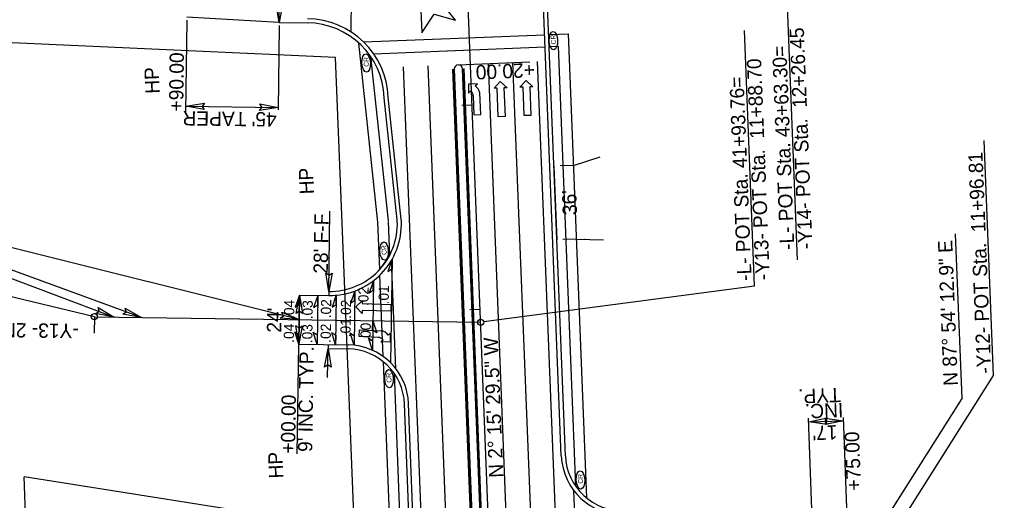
# Model space of a CAD drawing. Extents: x 1627861 to 1629601, y 761281 to 766239.
# Drawn here: x 1628159.8 to 1628635.6, y 764580 to 764815.3 of the extents above; entities that cross this region are included whole.
import ezdxf

# ---------------------------------------------------------------- set-up
doc = ezdxf.new("R2010")
doc.units = 0
for name, color, linetype in [('Cogo Default Point CELL', 7, 'Continuous'), ('Exist Other Culture Sign Leader', 7, 'Continuous'), ('Exist Property Tie Line Text', 7, 'Continuous'), ('Exist Right of Way Line Leader', 7, 'Continuous'), ('Exist Right of Way Monument Leader', 7, 'Continuous'), ('Exist Right of Way Monument Text', 7, 'Continuous'), ('Exist Utilities Gas Meter CELL', 7, 'Continuous'), ('Exist Utilities Gas Meter Cogo Elevation', 7, 'Continuous'), ('Exist Utilities Gas Meter Cogo Number', 7, 'Continuous'), ('Exist Utilities Gas UG Line', 7, 'Continuous'), ('Exist Utilities Other Unknown UG SUE Text', 7, 'Continuous'), ('Exist Utilities Power UG Cable SUE LOS B Cogo Elevation', 7, 'Continuous'), ('Exist Utilities Power UG Cable SUE LOS B Cogo Point CELL', 7, 'Continuous'), ('Exist Utilities Telephone UG Cable SUE LOS B Cogo Comment', 7, 'Continuous'), ('Exist Utilities Water Fire Hydrant Cogo Elevation', 7, 'Continuous'), ('Exist Utilities Water Fire Hydrant Cogo Number', 7, 'Continuous'), ('Exist Utilities Water Meter Cogo Elevation', 7, 'Continuous'), ('Exist Utilities Water UG Line SUE LOS B Cogo Number', 7, 'Continuous'), ('Exist Utilities Water Valve CELL', 7, 'Continuous'), ('Scratch_Level_0', 7, 'Continuous'), ('Scratch_Level_1', 7, 'Continuous'), ('Typical Terminator CELL', 7, 'Continuous')]:
    doc.layers.add(name, color=color, linetype=linetype)

msp = doc.modelspace()

# ---------------------------------------------------------------- linework, layer by layer
at = {"layer": 'Exist Property Tie Line Text'}
for p, q in [((1628380.89, 764773.37), (1628375.89, 764773.17)), ((1628384.83, 764673.44), (1628379.83, 764673.25)), ((1628296.38, 764668.47), (1628296.31, 764663.47))]:
    msp.add_line(p, q, dxfattribs=at)
at = {"layer": 'Exist Right of Way Line Leader'}
for p, q in [((1628534.55, 764828.18), (1628539.7, 764697.65)), ((1628518.82, 764684.98), (1628513.9, 764809.88)), ((1628635.55, 764641.16), (1628631.02, 764756.07)), ((1628620.22, 764629.95), (1628617.05, 764710.36)), ((1628106.19, 764707.24), (1628206.07, 764669.75)), ((1628196.39, 764669.89), (1628077.02, 764698.58)), ((1628386.55, 764667.49), (1628518.82, 764684.98)), ((1628586.95, 764564.08), (1628635.55, 764641.16)), ((1628577.69, 764562.5), (1628620.22, 764629.95)), ((1628166.92, 764468.18), (1628162.05, 764591.66)), ((1628387.99, 764555.85), (1628162.05, 764591.66))]:
    msp.add_line(p, q, dxfattribs=at)
for centre in [(1628196.39, 764669.89), (1628385.07, 764667.21)]:
    msp.add_circle(centre, 1.5, dxfattribs=at)
at = {"layer": 'Exist Right of Way Monument Leader'}
for p, q in [((1628383.44, 764783.82), (1628379.05, 764783.7)), ((1628379.05, 764783.7), (1628379.17, 764779.2)), ((1628382.44, 764782.73), (1628383.44, 764783.82)), ((1628391.64, 764781.65), (1628394.62, 764784.92)), ((1628393.14, 764781.71), (1628391.64, 764781.65)), ((1628393.68, 764767.72), (1628393.14, 764781.71)), ((1628394.62, 764784.92), (1628397.94, 764781.9)), ((1628397.94, 764781.9), (1628396.44, 764781.84)), ((1628396.44, 764781.84), (1628396.98, 764767.85)), ((1628404.24, 764782.15), (1628407.21, 764785.42)), ((1628405.74, 764782.21), (1628404.24, 764782.15)), ((1628406.28, 764768.22), (1628405.74, 764782.21)), ((1628407.21, 764785.42), (1628410.53, 764782.39)), ((1628410.53, 764782.39), (1628409.03, 764782.34)), ((1628409.03, 764782.34), (1628409.58, 764768.35)), ((1628379.17, 764779.2), (1628380.18, 764780.29)), ((1628381.42, 764777.84), (1628381.78, 764768.69)), ((1628385.08, 764768.82), (1628384.67, 764779.36)), ((1628381.78, 764768.69), (1628385.08, 764768.82)), ((1628396.98, 764767.85), (1628393.68, 764767.72)), ((1628409.58, 764768.35), (1628406.28, 764768.22)), ((1628324.07, 764674.67), (1628327.3, 764677.78)), ((1628327.3, 764677.78), (1628327.26, 764676.28)), ((1628327.26, 764676.28), (1628341.26, 764675.9)), ((1628327.13, 764671.48), (1628324.07, 764674.67)), ((1628327.17, 764672.98), (1628327.13, 764671.48)), ((1628341.17, 764672.6), (1628327.17, 764672.98)), ((1628341.26, 764675.9), (1628341.17, 764672.6)), ((1628325.79, 764660.14), (1628325.92, 764663.44)), ((1628325.92, 764663.44), (1628336.46, 764663.03)), ((1628334.93, 764659.79), (1628325.79, 764660.14)), ((1628336.3, 764657.53), (1628337.39, 764658.54)), ((1628340.79, 764657.41), (1628336.3, 764657.53)), ((1628339.82, 764660.8), (1628340.91, 764661.81)), ((1628340.91, 764661.81), (1628340.79, 764657.41))]:
    msp.add_line(p, q, dxfattribs=at)
for centre, radius, start, end in [((1628379.53, 764778.37), 5.25, 10.8898, 56.2015), ((1628378.17, 764777.72), 3.28, 2.2137, 51.8719), ((1628335.47, 764657.89), 5.25, 33.8044, 79.1161), ((1628334.82, 764656.53), 3.28, 38.134, 87.7921)]:
    msp.add_arc(centre, radius, start, end, dxfattribs=at)
at = {"layer": 'Exist Right of Way Monument Text'}
for p, q in [((1628424.43, 764601.84), (1628410.36, 764958.58)), ((1628346.31, 764717.41), (1628339.95, 764777.2)), ((1628430.34, 764743.87), (1628443.41, 764748.08)), ((1628346.35, 764716.64), (1628346.31, 764717.41)), ((1628431.76, 764707.89), (1628445.01, 764707.42)), ((1628436.26, 764707.71), (1628435.98, 764707.72)), ((1628296.55, 764680.46), (1628310.89, 764680.26)), ((1628296.21, 764656.48), (1628320.32, 764656.13)), ((1628360.72, 764352.1), (1628349.87, 764627.31))]:
    msp.add_line(p, q, dxfattribs=at)
for centre, radius, start, end in [((1628299.98, 764775.63), 40, 2.2582, 89.2561), ((1628311.37, 764715.26), 35, 269.2054, 2.2582), ((1628319.89, 764626.13), 30, 2.2582, 89.1726), ((1628454.41, 764603.02), 30, 182.2582, 272.0964)]:
    msp.add_arc(centre, radius, start, end, dxfattribs=at)
at = {"layer": 'Exist Utilities Gas Meter CELL'}
for p, q in [((1628486.22, 762102.11), (1628373.12, 764970.45)), ((1628196.39, 764669.89), (1628385.07, 764667.21)), ((1628196.39, 764669.89), (1628385.07, 764667.21))]:
    msp.add_line(p, q, dxfattribs=at)
at = {"layer": 'Exist Utilities Gas Meter Cogo Elevation'}
for p, q in [((1628426.43, 764601.91), (1628412.36, 764958.65)), ((1628286.55, 764813.81), (1628241.58, 764816.42)), ((1628286.64, 764813.8), (1628300.48, 764813.62)), ((1628344.33, 764717.2), (1628337.97, 764776.99)), ((1628344.35, 764716.56), (1628344.32, 764717.33)), ((1628344.35, 764716.56), (1628344.34, 764716.83)), ((1628310.91, 764682.26), (1628310.89, 764680.26)), ((1628310.55, 764656.27), (1628310.52, 764654.27)), ((1628310.52, 764654.27), (1628320.3, 764654.13)), ((1628358.72, 764352.02), (1628347.87, 764627.23))]:
    msp.add_line(p, q, dxfattribs=at)
for centre, radius, start, end in [((1628299.98, 764775.63), 38, 2.2582, 89.2561), ((1628311.37, 764715.26), 33, 269.2054, 2.2582), ((1628319.89, 764626.13), 28, 2.2582, 89.1726), ((1628454.41, 764603.02), 28, 182.2582, 272.0964)]:
    msp.add_arc(centre, radius, start, end, dxfattribs=at)
at = {"layer": 'Exist Utilities Gas Meter Cogo Number'}
for points in [[(1628288.3, 764822.78), (1628286.64, 764813.8), (1628285.15, 764822.87), (1628286.74, 764821.7)], [(1628250.08, 764771.19), (1628241.1, 764772.86), (1628250.17, 764774.34), (1628249, 764772.76)], [(1628277.12, 764773.94), (1628286.1, 764772.28), (1628277.03, 764770.79), (1628278.2, 764772.38)], [(1628312.59, 764691.24), (1628310.92, 764682.26), (1628309.44, 764691.34), (1628311.03, 764690.16)], [(1628294.87, 764671.49), (1628296.55, 764680.46), (1628298.02, 764671.39), (1628296.44, 764672.56)], [(1628198.19, 764674.36), (1628206.07, 764669.75), (1628197.04, 764671.43), (1628198.67, 764672.53)], [(1628211.46, 764674.11), (1628219.39, 764669.56), (1628210.34, 764671.16), (1628211.97, 764672.27)], [(1628288.02, 764672.16), (1628296.38, 764668.47), (1628287.21, 764669.12), (1628288.71, 764670.39)], [(1628297.88, 764665.45), (1628296.21, 764656.48), (1628294.74, 764665.55), (1628296.32, 764664.37)], [(1628308.84, 764645.29), (1628310.52, 764654.27), (1628311.99, 764645.2), (1628310.41, 764646.37)], [(1628554.33, 764617.21), (1628545.28, 764618.43), (1628554.27, 764620.36), (1628553.17, 764618.72)], [(1628553.22, 764620.27), (1628562.27, 764619.05), (1628553.28, 764617.12), (1628554.37, 764618.76)]]:
    msp.add_lwpolyline(points, close=True, dxfattribs=at)
at = {"layer": 'Exist Utilities Gas UG Line'}
for p, q in [((1628408.48, 763242.45), (1628347.37, 764792.06)), ((1628420.44, 763243.74), (1628359.36, 764792.53)), ((1628385.15, 764443.28), (1628371.43, 764791.01)), ((1628388.67, 764493.5), (1628376.93, 764791.23)), ((1628400.66, 764493.93), (1628388.84, 764793.7)), ((1628462.18, 763238.38), (1628400.83, 764794.17)), ((1628474.17, 763238.85), (1628412.82, 764794.64))]:
    msp.add_line(p, q, dxfattribs=at)
at = {"layer": 'Exist Utilities Other Unknown UG SUE Text'}
for p, q in [((1628385.9, 764443.31), (1628372.18, 764791.04)), ((1628372.18, 764791.04), (1628385.9, 764443.31)), ((1628376.18, 764791.2), (1628387.92, 764493.43)), ((1628387.92, 764493.43), (1628376.18, 764791.2))]:
    msp.add_line(p, q, dxfattribs=at)
msp.add_arc((1628374.18, 764791.12), 2, 2.2582, 182.2582, dxfattribs=at)
msp.add_arc((1628374.18, 764791.12), 2, 2.2582, 182.2582, dxfattribs=at)
at = {"layer": 'Exist Utilities Power UG Cable SUE LOS B Cogo Elevation'}
msp.add_lwpolyline([(1628355.85, 764819.61), (1628356.28, 764808.81), (1628362.28, 764817.8), (1628372.71, 764814.86), (1628366, 764823.37), (1628372.01, 764832.38), (1628361.86, 764828.63), (1628355.15, 764837.12), (1628355.58, 764826.31), (1628345.42, 764822.55), (1628355.85, 764819.61)], dxfattribs=at)
at = {"layer": 'Exist Utilities Telephone UG Cable SUE LOS B Cogo Comment'}
for p, q in [((1628327.85, 764804.33), (1628416.31, 764807.82)), ((1628332.79, 764798.52), (1628416.54, 764801.82)), ((1628343.69, 764644.4), (1628341.59, 764697.6)), ((1628337.45, 764650.46), (1628335.88, 764690.27)), ((1628432.93, 764525.93), (1628430.61, 764584.76))]:
    msp.add_line(p, q, dxfattribs=at)
at = {"layer": 'Exist Utilities Water Fire Hydrant Cogo Elevation'}
for centre in [(1628420.58, 764804.92), (1628329.16, 764793.98), (1628337.89, 764702.01), (1628340.29, 764639.52), (1628433.84, 764590.11)]:
    msp.add_ellipse(centre, major_axis=(-0.18, 4.48), ratio=0.462467, dxfattribs=at)
at = {"layer": 'Exist Utilities Water Fire Hydrant Cogo Number'}
for p, q in [((1628314.21, 764796.74), (1628139.67, 764804.6)), ((1628318.39, 764691.37), (1628314.21, 764796.74)), ((1628320.13, 764646.7), (1628318.39, 764691.37)), ((1628333.03, 764325.09), (1628320.13, 764646.7))]:
    msp.add_line(p, q, dxfattribs=at)
at = {"layer": 'Exist Utilities Water Meter Cogo Elevation'}
msp.add_line((1628196.39, 764669.89), (1628196.27, 764661.89), dxfattribs=at)
at = {"layer": 'Exist Utilities Water UG Line SUE LOS B Cogo Number'}
for p, q in [((1628322.41, 764872.86), (1628321.58, 764809.3)), ((1628341.8, 764697.97), (1628341.08, 764647.36)), ((1628332.65, 764687.47), (1628332.17, 764653.5)), ((1628323.58, 764682.46), (1628323.2, 764655.95)), ((1628296.55, 764680.46), (1628296.21, 764656.48)), ((1628305.55, 764680.34), (1628305.21, 764656.35)), ((1628314.55, 764680.41), (1628314.21, 764656.22))]:
    msp.add_line(p, q, dxfattribs=at)
at = {"layer": 'Exist Utilities Water Valve CELL'}
for p, q in [((1628418.31, 764807.89), (1628427.8, 764808.27)), ((1628427.8, 764808.27), (1628436.75, 764581.29)), ((1628334.88, 764716.19), (1628325.57, 764803.73)), ((1628423.04, 764802.08), (1628418.54, 764801.9)), ((1628431.52, 764586.88), (1628423.04, 764802.08)), ((1628331.29, 764797.16), (1628339.85, 764716.72)), ((1628335.76, 764693.09), (1628334.86, 764716.07)), ((1628339.85, 764716.43), (1628340.5, 764699.81)), ((1628340.5, 764699.81), (1628335.76, 764693.09)), ((1628350.14, 764328.49), (1628337.55, 764647.86)), ((1628342.77, 764642.27), (1628354.88, 764335.22))]:
    msp.add_line(p, q, dxfattribs=at)
at = {"layer": 'Scratch_Level_0'}
for p, q in [((1628286.64, 764813.8), (1628287.26, 764861.8)), ((1628241.06, 764769.9), (1628241.65, 764814.89)), ((1628286.62, 764812.37), (1628286.08, 764771.04)), ((1628374.1, 764793.12), (1628409.08, 764794.49)), ((1628241.1, 764772.86), (1628286.1, 764772.28)), ((1628420.85, 764743.49), (1628422.26, 764707.52)), ((1628310.92, 764682.26), (1628311.47, 764721.5)), ((1628219.39, 764669.56), (1628115.69, 764707.44)), ((1628296.38, 764668.47), (1628134.8, 764708.93)), ((1628296.21, 764656.48), (1628296.55, 764680.46)), ((1628295.45, 764602.83), (1628296.21, 764656.48)), ((1628310.32, 764640.09), (1628310.52, 764654.27)), ((1628546.84, 764575.83), (1628545.21, 764620.35)), ((1628563.83, 764576.4), (1628562.21, 764620.66)), ((1628545.28, 764618.43), (1628562.27, 764619.05))]:
    msp.add_line(p, q, dxfattribs=at)
at = {"layer": 'Scratch_Level_1'}
for p, q in [((1628430.34, 764743.87), (1628423.84, 764743.61)), ((1628431.76, 764707.89), (1628425.26, 764707.64))]:
    msp.add_line(p, q, dxfattribs=at)
at = {"layer": 'Typical Terminator CELL'}
for points in [[(1628341.8, 764697.97), (1628339.72, 764692), (1628341.73, 764693.34)], [(1628332.65, 764687.47), (1628330.57, 764681.5), (1628332.59, 764682.85)], [(1628323.58, 764682.46), (1628321.49, 764676.49), (1628323.51, 764677.83)], [(1628296.55, 764680.46), (1628294.46, 764674.49), (1628296.48, 764675.84)], [(1628305.55, 764680.34), (1628303.46, 764674.37), (1628305.48, 764675.71)], [(1628314.55, 764680.53), (1628312.47, 764674.55), (1628314.48, 764675.9)], [(1628332.37, 764667.96), (1628334.29, 764661.93), (1628332.31, 764663.33)], [(1628296.21, 764656.48), (1628294.29, 764662.5), (1628296.27, 764661.1)], [(1628305.21, 764656.35), (1628303.29, 764662.37), (1628305.27, 764660.97)], [(1628314.21, 764656.22), (1628312.29, 764662.24), (1628314.27, 764660.84)], [(1628323.2, 764655.95), (1628321.29, 764661.97), (1628323.27, 764660.57)], [(1628332.17, 764653.5), (1628330.25, 764659.53), (1628332.23, 764658.13)]]:
    msp.add_lwpolyline(points, close=True, dxfattribs=at)

# ---------------------------------------------------------------- texts
at = {"layer": 'Cogo Default Point CELL'}
for s, p in [('N 87%%d 54\' 12.9" E', (1628618.17, 764636.23)), ('N 2%%d 15\' 29.5" W', (1628396.14, 764591.28))]:
    msp.add_text(s, height=7, rotation=92.2582, dxfattribs=at).set_placement(p)
at = {"layer": 'Exist Other Culture Sign Leader'}
for s, rotation, p in [('HP', 92.2582, (1628228.27, 764779.08)), ('HP', 92.2582, (1628303.7, 764729.9)), ('-Y13- 2ND RAINBOW STREET', 179.1874, (1628188.77, 764666.35)), ('HP', 92.2582, (1628288.72, 764590.92))]:
    msp.add_text(s, height=7, rotation=rotation, dxfattribs=at).set_placement(p)
at = {"layer": 'Exist Right of Way Line Leader'}
for s, rotation, p in [('-Y14- POT Sta.  12+26.45', 92.2582, (1628547.16, 764703.06)), ('-L- POT Sta. 43+63.30=', 92.2582, (1628538.3, 764702.71)), ('-Y13- POT Sta.  11+88.70', 92.2582, (1628526.3, 764687.93)), ('-L- POT Sta. 41+93.76=', 92.2582, (1628517.44, 764687.58)), ('-Y12- POT Sta.  11+96.81', 92.296, (1628634.48, 764642.22))]:
    msp.add_text(s, height=7, rotation=rotation, dxfattribs=at).set_placement(p)
at = {"layer": 'Exist Utilities Power UG Cable SUE LOS B Cogo Point CELL'}
for s, rotation, p in [('+90.00', 89.2561, (1628239.79, 764770.24)), ("45' TAPER", 179.2561, (1628285.48, 764769.86)), ("28' F-F", 89.1227, (1628310.38, 764690.9)), ("24'", 89.1227, (1628287.63, 764662.04)), ("9' INC. TYP.", 89.1227, (1628302.79, 764603.72)), ('TYP.', 182.0964, (1628560.81, 764635.17)), ('+00.00', 89.1227, (1628294.4, 764602.84)), ('INC.', 182.0964, (1628562.03, 764627.78)), ("17'", 182.0964, (1628559.21, 764616.92)), ('+75.00', 92.0586, (1628570.86, 764585))]:
    msp.add_text(s, height=7, rotation=rotation, dxfattribs=at).set_placement(p)
at = {"layer": 'Exist Utilities Water Fire Hydrant Cogo Elevation'}
for p in [(1628421.83, 764803.09), (1628330.42, 764792.15), (1628339.15, 764700.17), (1628341.54, 764637.68), (1628435.09, 764588.27)]:
    msp.add_text('CR', height=2.4, rotation=92.2582, dxfattribs=at).set_placement(p)
at = {"layer": 'Exist Utilities Water UG Line SUE LOS B Cogo Number'}
for s, p in [('.02', (1628330.22, 764675.09)), ('.01', (1628340.16, 764675.91)), ('.04', (1628293.96, 764668.8)), ('.03', (1628302.96, 764668.62)), ('.02', (1628311.96, 764669.13)), ('.02', (1628321.7, 764668.88)), ('.01', (1628321.49, 764659.81)), ('.04', (1628293.83, 764657.14)), ('.03', (1628302.82, 764656.95)), ('.02', (1628311.83, 764657.15)), ('.00', (1628331.29, 764657.64))]:
    msp.add_text(s, height=5, rotation=89.1874, dxfattribs=at).set_placement(p)
at = {"layer": 'Scratch_Level_0'}
for s, rotation, p in [('+20.00', 182.2582, (1628411.38, 764794.04)), ("36'", 92.2582, (1628432.19, 764719.75))]:
    msp.add_text(s, height=7, rotation=rotation, dxfattribs=at).set_placement(p)

doc.saveas('drawing.dxf')
